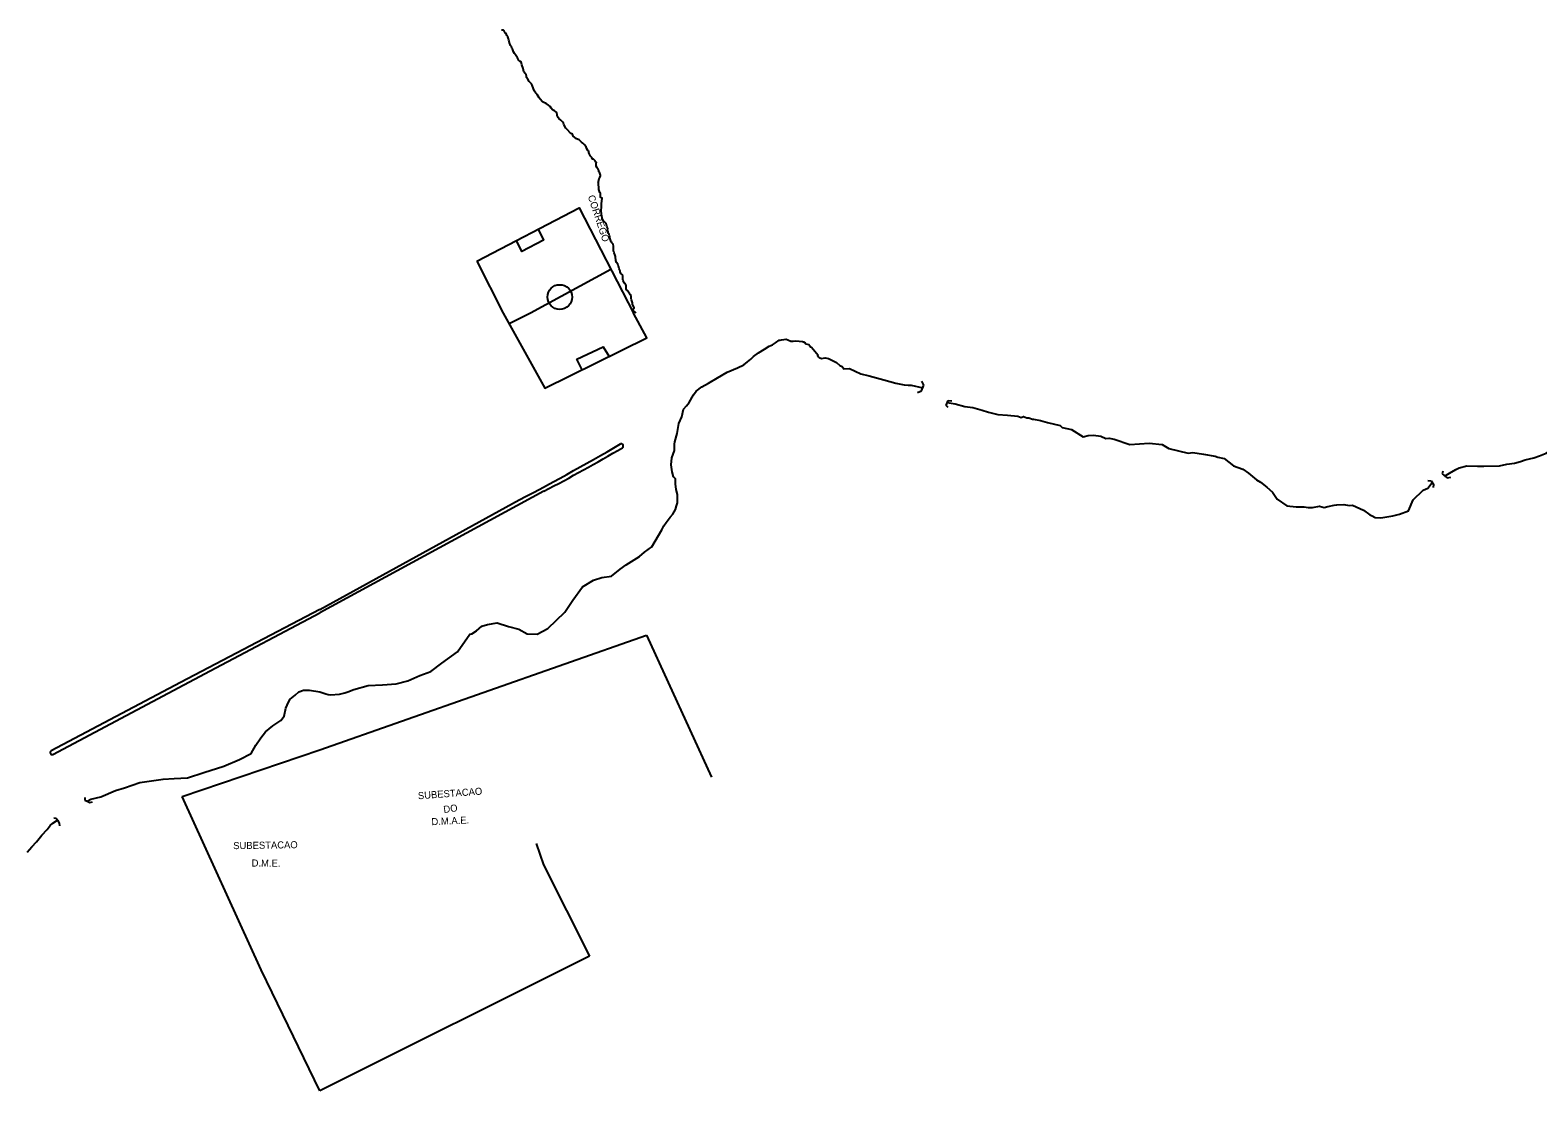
# Model space of a CAD drawing. Extents: x 325899 to 364828, y 7568995 to 7592502.
# Drawn here: x 340717 to 341572, y 7588060 to 7588663 of the extents above; entities that cross this region are included whole.
import ezdxf

# ---------------------------------------------------------------- set-up
doc = ezdxf.new("R2010")
doc.units = 0
for name, color, linetype in [('EDIFEXISTENT', 7, 'Continuous'), ('EDIFIDENTIF', 7, 'Continuous'), ('EDIFOBRAEXIS', 7, 'Continuous')]:
    doc.layers.add(name, color=color, linetype=linetype)

msp = doc.modelspace()

# ---------------------------------------------------------------- linework, layer by layer
at = {"layer": 'EDIFEXISTENT'}
for p, q in [((341220.36, 7588456.94), (341222.79, 7588457.76)), ((341222.79, 7588457.76), (341224.09, 7588460.95)), ((341224.09, 7588460.95), (341222.85, 7588463.32)), ((341236.73, 7588449.52), (341237.81, 7588452.41)), ((341237.87, 7588448.3), (341236.73, 7588449.52)), ((341237.81, 7588452.41), (341239.84, 7588452.23)), ((341510.04, 7588406.94), (341511.77, 7588406.7)), ((341511.77, 7588406.7), (341513.26, 7588404.69)), ((341513.26, 7588404.69), (341512.92, 7588403.04)), ((341518.43, 7588412.2), (341518.12, 7588410.62)), ((341518.12, 7588410.62), (341520.86, 7588408.38)), ((341520.86, 7588408.38), (341522.97, 7588408.78)), ((340881.39, 7588254), (341066.77, 7588319.07)), ((341066.77, 7588319.07), (341103.55, 7588238.54)), ((340803.33, 7588227.5), (340881.39, 7588254)), ((340748.18, 7588227.04), (340748.16, 7588225.44)), ((340748.16, 7588225.44), (340749.48, 7588224.95)), ((340749.48, 7588224.95), (340750.93, 7588224.09)), ((340750.93, 7588224.09), (340752.5, 7588224.57)), ((340848.05, 7588129.19), (340803.33, 7588227.5)), ((340730.45, 7588215.5), (340731.83, 7588215.2)), ((340731.83, 7588215.2), (340732.66, 7588214.1)), ((340732.66, 7588214.1), (340733.6, 7588212.4)), ((340733.6, 7588212.4), (340733.78, 7588210.8)), ((341004.13, 7588200.8), (341008.23, 7588188.69)), ((341008.23, 7588188.69), (341034.36, 7588136.93)), ((341034.36, 7588136.93), (340881.39, 7588060.42)), ((340854.29, 7588116.27), (340848.05, 7588129.19)), ((340881.39, 7588060.42), (340854.29, 7588116.27))]:
    msp.add_line(p, q, dxfattribs=at)
at = {"layer": 'EDIFOBRAEXIS'}
for points in [[(341060.91, 7588501.91), (341059.87, 7588502.94), (341059.36, 7588503.32), (341059.11, 7588503.65), (341058.88, 7588504), (341059.71, 7588504.87), (341058.82, 7588506.95), (341058.84, 7588507.81), (341058.2, 7588509.56), (341058.05, 7588510.25), (341058.05, 7588510.55), (341057.97, 7588511.52), (341057.89, 7588512.03), (341057.79, 7588512.31), (341057.3, 7588512.76), (341056.13, 7588514.46), (341055.88, 7588514.81), (341055.19, 7588515.42), (341055.16, 7588515.7), (341055.13, 7588516.77), (341055.23, 7588517.33), (341055.21, 7588517.66), (341055.08, 7588518.01), (341054.32, 7588519.03), (341053.42, 7588520.24), (341053.32, 7588521.16), (341053.34, 7588521.97), (341053.27, 7588522.88), (341053.09, 7588523.59), (341052.19, 7588524.46), (341051.81, 7588525.29), (341051.71, 7588526.03), (341051.3, 7588527.09), (341050.94, 7588528.03), (341050.94, 7588528.29), (341050.58, 7588529.05), (341050.48, 7588529.66), (341049.66, 7588530.62), (341049.28, 7588531.81), (341049.25, 7588532.35), (341049.2, 7588533.23), (341049.17, 7588534.15), (341048.92, 7588534.71), (341048.43, 7588536.18), (341048.17, 7588536.99), (341048.02, 7588537.35), (341047.94, 7588538.74), (341047.97, 7588539.02), (341048.04, 7588539.99), (341047.81, 7588541.1), (341047.2, 7588541.61), (341047.07, 7588541.86), (341047.02, 7588542.19), (341046.51, 7588542.62), (341046.56, 7588542.9), (341046.3, 7588543.46), (341046.15, 7588544.07), (341045.87, 7588545.21), (341045.79, 7588545.82), (341045.56, 7588546.63), (341045.25, 7588547.19), (341045, 7588547.75), (341044.97, 7588548), (341044.61, 7588548.74), (341044.69, 7588550.09), (341044.61, 7588550.42), (341044.25, 7588551.33), (341043.77, 7588552.75), (341042.98, 7588553.76), (341042.31, 7588554.42), (341041.52, 7588555.74), (341041.52, 7588555.97), (341041.21, 7588557.95), (341041.03, 7588560.29), (341041.13, 7588561.91), (341041.27, 7588563.92), (341041.62, 7588567.14), (341041.62, 7588567.14), (341040.71, 7588567.62), (341040.6, 7588568.33), (341040.67, 7588569.78), (341040.29, 7588570.44), (341039.86, 7588571.48), (341039.75, 7588572.12), (341039.68, 7588572.67), (341039.57, 7588575.52), (341039.49, 7588576.15), (341039.34, 7588576.43), (341039.46, 7588576.69), (341039.77, 7588577.2), (341039.69, 7588577.75), (341039.82, 7588578.01), (341039.89, 7588578.29), (341040.07, 7588578.59), (341040.17, 7588578.85), (341040.6, 7588579.92), (341040.62, 7588580.22), (341040.47, 7588580.78), (341040.24, 7588581.41), (341039.83, 7588581.94), (341039.75, 7588582.22), (341039.68, 7588582.83), (341039.42, 7588583.34), (341039.19, 7588584.03), (341038.78, 7588584.51), (341038.15, 7588585.34), (341038.07, 7588586.31), (341038.24, 7588587.1), (341038.27, 7588587.35), (341037.86, 7588587.7), (341037.58, 7588588.39), (341036.66, 7588589.3), (341036.41, 7588589.35), (341036.15, 7588589.43), (341035.62, 7588590.24), (341034.88, 7588590.97), (341034.57, 7588591.89), (341034.4, 7588592.14), (341034.22, 7588592.47), (341034.06, 7588593.1), (341034.01, 7588593.81), (341033.48, 7588594.35), (341032.89, 7588595.26), (341032.48, 7588596.38), (341031.41, 7588597.72), (341030.65, 7588598.35), (341029.78, 7588599.06), (341028.99, 7588599.87), (341028.56, 7588600.4), (341027.06, 7588600.83), (341025.96, 7588601.79), (341025.12, 7588602.32), (341024.72, 7588603.49), (341023.98, 7588603.92), (341023.42, 7588604.28), (341021.81, 7588606.05), (341021.05, 7588606.99), (341019.9, 7588608.99), (341019.54, 7588609.78), (341019.08, 7588610.59), (341018.58, 7588611.07), (341018.07, 7588611.42), (341017.02, 7588612.39), (341016.56, 7588613.04), (341016.21, 7588613.83), (341016.05, 7588614.19), (341015.95, 7588614.69), (341015.82, 7588615.4), (341015.64, 7588616.01), (341015.03, 7588616.49), (341014.45, 7588616.75), (341013.38, 7588617.33), (341012.61, 7588618.34), (341012.03, 7588619.18), (341011.09, 7588619.94), (341009.71, 7588620.95), (341008.54, 7588621.53), (341007.7, 7588621.89), (341006.4, 7588623.33), (341005.87, 7588624.14), (341004.7, 7588626.04), (341004.01, 7588626.73), (341003.09, 7588628.02), (341002.53, 7588629.21), (341001.79, 7588631.27), (341001.4, 7588632.18), (341000.84, 7588632.71), (341000.13, 7588633.5), (340999.37, 7588634.69), (340998.7, 7588635.68), (340998.6, 7588636.49), (340998.45, 7588637.12), (340997.81, 7588637.91), (340997.22, 7588638.85), (340996.66, 7588640.73), (340995.97, 7588642.93), (340995.56, 7588644.51), (340995.4, 7588644.79), (340995.12, 7588644.71), (340994.87, 7588644.86), (340994.29, 7588645.32), (340993.47, 7588646.84), (340993.19, 7588647.42), (340992.42, 7588648.64), (340991.89, 7588649.27), (340991.28, 7588650.36), (340990.74, 7588651.93), (340990.28, 7588652.42), (340990.05, 7588653.28), (340989.62, 7588653.91), (340989.39, 7588654.45), (340989.26, 7588654.8), (340988.62, 7588656.88), (340988.44, 7588657.67), (340988.23, 7588658.2), (340988.03, 7588658.86), (340987.52, 7588659.57), (340987.29, 7588660.08), (340987.06, 7588660.71), (340986.52, 7588660.86), (340986.24, 7588661.37), (340985.91, 7588662.21), (340985.76, 7588662.46), (340985.5, 7588662.59), (340984.39, 7588662.58)], [(340970.46, 7588531.38), (341028.44, 7588561.62), (341059.32, 7588501.91)], [(341005.34, 7588549.58), (341008.3, 7588543.42), (340995.99, 7588536.89), (340992.9, 7588543.08)], [(340970.46, 7588531.38), (340985.43, 7588501.91)], [(341046.5, 7588526.7), (341000.83, 7588501.91)], [(340985.43, 7588501.91), (341009.06, 7588459.26), (341066.96, 7588487.88), (341059.32, 7588501.91)], [(341000.83, 7588501.91), (340988.73, 7588495.95)], [(340881.39, 7588286.89), (340884.72, 7588285.77), (340886.17, 7588285.38), (340887.45, 7588285.2), (340892.64, 7588285.6), (340895.5, 7588286.34), (340897.23, 7588286.91), (340900.64, 7588288.24), (340908.87, 7588290.46), (340916.9, 7588290.92), (340924.67, 7588291.56), (340931.32, 7588293.14), (340938.06, 7588296.14), (340944.44, 7588298.41), (340950.65, 7588303.25), (340959.48, 7588309.72), (340966.51, 7588319.68), (340967.55, 7588319.91), (340970.37, 7588321.63), (340973.38, 7588324.16), (340976.43, 7588325.17), (340981.91, 7588326.04), (340988.41, 7588324.02), (340994.37, 7588322.61), (340999.08, 7588319.85), (341004.6, 7588319.71), (341010.73, 7588322.89), (341020.35, 7588332.11), (341024.96, 7588338.96), (341030.36, 7588346.51), (341036.57, 7588350.43), (341041.32, 7588351.86), (341046.93, 7588352.66), (341051.79, 7588356.66), (341055.18, 7588359.11), (341062.71, 7588363.82), (341065.56, 7588366.22), (341069.75, 7588369.28), (341075.49, 7588378.84), (341076.54, 7588381.25), (341077.94, 7588383.15), (341080.13, 7588386.14), (341081.63, 7588387.74), (341083.24, 7588390.55), (341083.83, 7588392.48), (341084.27, 7588394.26), (341084.35, 7588396.19), (341084.25, 7588399.03), (341083.47, 7588401.85), (341083.15, 7588404.95), (341083.11, 7588406.73), (341083.08, 7588407.95), (341082.05, 7588408.94), (341081.21, 7588411.78), (341080.67, 7588415.72), (341081.03, 7588419.88), (341082.57, 7588423.94), (341082.68, 7588427.63), (341082.86, 7588428.92), (341084.04, 7588433.61), (341085.15, 7588439.35), (341086.76, 7588443.13), (341087.71, 7588447.44), (341089.49, 7588449.24), (341090.89, 7588451.24), (341093.42, 7588455.63), (341094.94, 7588457.63), (341098.02, 7588460.01), (341101.84, 7588462.26), (341107.05, 7588465.29), (341112.49, 7588468.45), (341118.41, 7588470.9), (341121.85, 7588472.54), (341124.04, 7588474.24), (341125.87, 7588475.78), (341126.89, 7588476.69), (341127.42, 7588477.28), (341130.19, 7588479.38), (341133.6, 7588481.53), (341136.37, 7588483.17), (341138.13, 7588483.98), (341139.81, 7588485.12), (341142.04, 7588486.56), (341142.48, 7588486.56), (341143.39, 7588486.76), (341146.01, 7588487.23), (341146.97, 7588486.77), (341148.54, 7588486.11), (341149.53, 7588486.08), (341149.97, 7588485.98), (341151.36, 7588486.13), (341155.25, 7588485.81), (341155.7, 7588485.73), (341156.69, 7588485.02), (341157.15, 7588484.51), (341158.75, 7588484.1), (341159.45, 7588483.46), (341159.68, 7588482.75), (341160.29, 7588482.65), (341164.06, 7588478.16), (341163.66, 7588477.82), (341164.36, 7588477.05), (341164.67, 7588476.82), (341166.06, 7588476.24), (341168.02, 7588476.51), (341169.95, 7588476.18), (341174.47, 7588473.93), (341176.44, 7588472.25), (341177.66, 7588471.56), (341178.69, 7588470.26), (341181.94, 7588470.58), (341188.28, 7588467.49), (341193.08, 7588466.34), (341201.28, 7588464.06), (341208.07, 7588462.15), (341212.89, 7588461.26), (341215.11, 7588460.95), (341216.82, 7588460.95), (341223.46, 7588459.54)], [(341030.16, 7588469.69), (341027.2, 7588475.78), (341042.2, 7588482.8), (341045.57, 7588477.3)], [(341237.36, 7588451.2), (341241.81, 7588450.49), (341247.25, 7588449.01), (341251.89, 7588448.33), (341257.09, 7588446.9), (341260.72, 7588445.67), (341266.12, 7588444.44), (341271.48, 7588444.07), (341277.29, 7588443.39), (341279.2, 7588442.73), (341280.57, 7588443.16), (341282.55, 7588442.52), (341283.64, 7588442.41), (341285.64, 7588441.72), (341286.2, 7588441.7), (341290.31, 7588440.9), (341294.22, 7588439.92), (341301.38, 7588438.08), (341302.47, 7588437.01), (341307.74, 7588435.78), (341314.49, 7588431.8), (341317.36, 7588432.52), (341320.31, 7588432.72), (341324.44, 7588432.06), (341327.38, 7588430.75), (341329.26, 7588431.02), (341331.98, 7588430.43), (341340.86, 7588427.33), (341351.91, 7588428.12), (341359.22, 7588427.34), (341363.02, 7588425.12), (341373.91, 7588422.53), (341376.72, 7588422.8), (341382.74, 7588421.85), (341389.31, 7588420.78), (341390.89, 7588420.22), (341394.35, 7588419.41), (341399.81, 7588415.2), (341404.99, 7588413.41), (341408.15, 7588411.11), (341412.84, 7588407.32), (341415.07, 7588405.96), (341418.62, 7588403.21), (341421.91, 7588400.23), (341424.42, 7588396.34), (341429.94, 7588392.57), (341435.32, 7588391.9), (341439.74, 7588392.06), (341442.1, 7588391.5), (341444.54, 7588391.59), (341448.48, 7588392.42), (341451.12, 7588391.52), (341453.2, 7588392.13), (341456.88, 7588392.98), (341458.28, 7588393.16), (341462.33, 7588393.22), (341465.31, 7588392.66), (341467.22, 7588392.85), (341473.51, 7588390.04), (341477.06, 7588387.47), (341478.3, 7588386.91), (341480.18, 7588385.89), (341483.3, 7588385.8), (341490.06, 7588386.9), (341493.89, 7588387.78), (341499.08, 7588389.75), (341501.63, 7588395.99), (341507.41, 7588401.43), (341510.05, 7588402.57), (341512.35, 7588405.76)], [(341519.42, 7588409.45), (341523.26, 7588411.68), (341523.61, 7588411.8), (341525.77, 7588413.22), (341527.68, 7588414.13), (341532.02, 7588415.16), (341538.14, 7588415.04), (341541.75, 7588415.03), (341550.56, 7588415.24), (341554.78, 7588416.14), (341559.17, 7588416.69), (341562.53, 7588417.62), (341565.17, 7588418.6), (341570.15, 7588419.75), (341573.33, 7588420.97), (341577.06, 7588422.48), (341581.49, 7588425.21), (341585.1, 7588427.31), (341586.57, 7588427.84), (341587.77, 7588428.62), (341590.49, 7588430.11), (341590.49, 7588430.11)], [(341008.49, 7588400.83), (340881.39, 7588331.74)], [(340881.39, 7588333.68), (340990.7, 7588393.87)], [(340881.39, 7588333.68), (340802.36, 7588292.19), (340728.94, 7588253.47)], [(340729.99, 7588251.37), (340819.12, 7588298.95), (340881.39, 7588331.74)], [(340749.48, 7588224.95), (340751.46, 7588226.07), (340757.25, 7588227.29), (340765.53, 7588230.9), (340770.56, 7588232.47), (340779.37, 7588235.47), (340792.53, 7588237.28), (340798.68, 7588237.73), (340806.32, 7588238.17), (340815.67, 7588241.19), (340826.87, 7588244.8), (340835.89, 7588248.61), (340842.44, 7588251.96), (340845.16, 7588256.69), (340847.95, 7588260.9), (340850.64, 7588264.28), (340854.68, 7588267.69), (340859.36, 7588270.76), (340861.24, 7588273.2), (340862.17, 7588277.7), (340863.67, 7588281.05), (340864.66, 7588282.78), (340867.48, 7588285.11), (340869.57, 7588286.87), (340872.18, 7588287.81), (340874.16, 7588287.88), (340875.56, 7588287.81), (340881.39, 7588286.89)], [(340715.34, 7588195.97), (340717.98, 7588198.96), (340720.75, 7588201.71), (340723.62, 7588205.65), (340726.72, 7588208.74), (340728.47, 7588211.06), (340729.97, 7588212.43), (340732.66, 7588214.1)]]:
    msp.add_lwpolyline(points, dxfattribs=at)
msp.add_circle((341017.53, 7588511.06), 7.02, dxfattribs=at)
for centre, radius, start, end in [((340293.61, 7589729.22), 1506.35, 297.56568, 300.22438), ((340469.28, 7589427.93), 1160.04, 297.69863, 300.22042), ((341052.33, 7588426.47), 1.25, 312.00676, 110.55502), ((340729.62, 7588252.5), 1.19, 125.17296, 288.22596)]:
    msp.add_arc(centre, radius, start, end, dxfattribs=at)

# ---------------------------------------------------------------- texts
at = {"layer": 'EDIFIDENTIF'}
for s, rotation, p in [('CORREGO', 288.36748, (341033.34, 7588568.21)), ('SUBESTACAO', 4.25571, (340937.18, 7588225.93)), ('D.M.A.E.', 2.73106, (340944.82, 7588211.22)), ('DO', 7.71794, (340951.79, 7588218.14)), ('SUBESTACAO', 0.86926, (340832.3, 7588197.63)), ('D.M.E.', 359.51487, (340842.7, 7588187.78))]:
    msp.add_text(s, height=4, rotation=rotation, dxfattribs=at).set_placement(p)

doc.saveas('drawing.dxf')
